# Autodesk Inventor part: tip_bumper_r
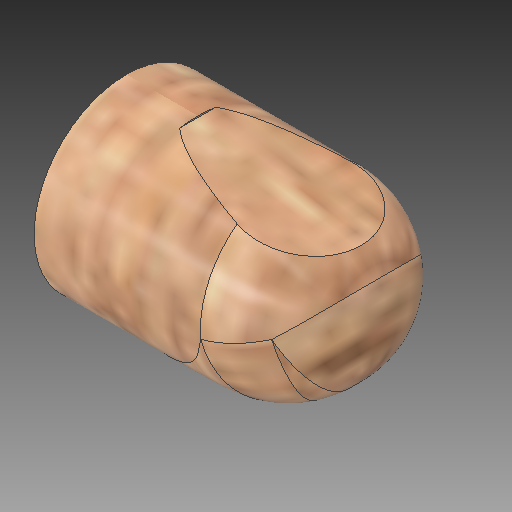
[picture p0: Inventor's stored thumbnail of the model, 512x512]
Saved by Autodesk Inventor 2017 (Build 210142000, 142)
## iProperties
Created: 2017-05
Part Number: tip_bumper_r
Material: Generic
Document SubType Name: Modeling
Designer: alez_
Density: 1 g/cm^3
Appearance: Default
Author: alez_
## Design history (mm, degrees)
derived "Tip_bumper.ipt" dims "d0" = 11
feature "Solid1::Tip_bumper.ipt" dims "d0" = 11
tag "TaggingFeature1"
body "Solid1"
